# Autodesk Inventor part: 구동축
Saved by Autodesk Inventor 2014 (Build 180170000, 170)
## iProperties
Created: 2026-05
Part Number: 구동축
Material: 일반
Document SubType Name: Modeling
Designer: dg
Density: 1 g/cm^3
Appearance: 기본값
Author: dg
Author: jhkim
Creation Date: 2026-04-23
Sending System: Autodesk Inventor 2027
Preprocessor: ST-DEVELOPER v20.1
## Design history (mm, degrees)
node "구동축1"
node "솔리드1"
node "기준1"
